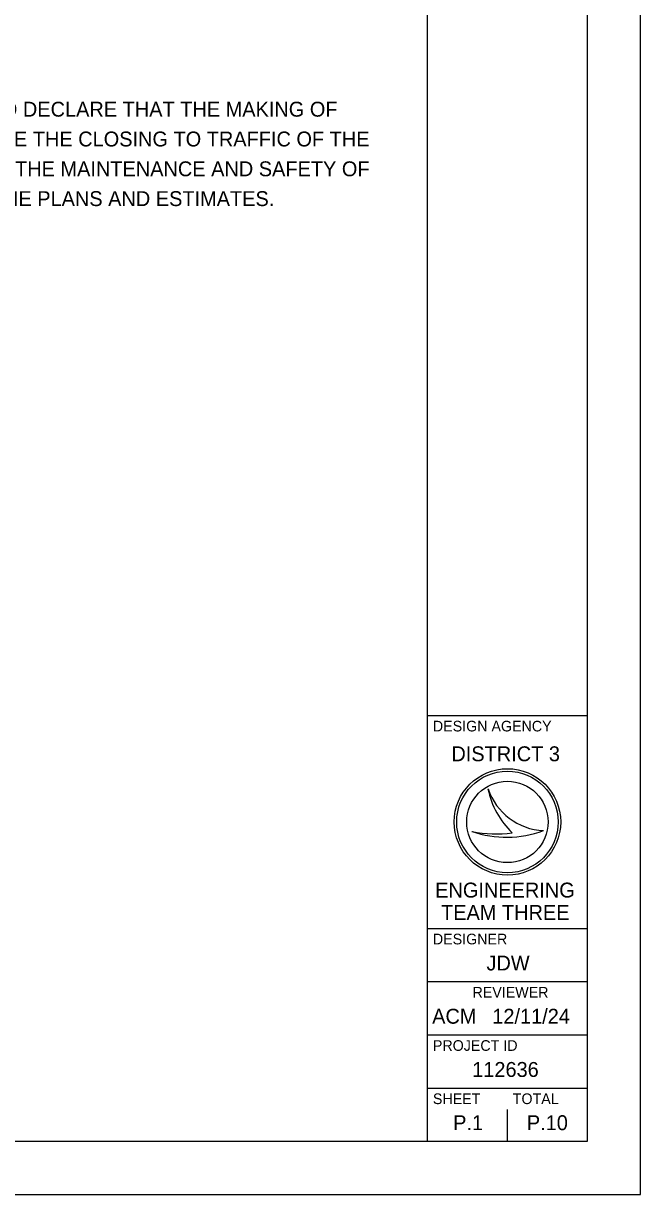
# Model space of a CAD drawing. Extents: x 0 to 170000, y 0 to 110000.
# Drawn here: x 141026 to 170000, y 0 to 55000 of the extents above; entities that cross this region are included whole.
import ezdxf

# ---------------------------------------------------------------- set-up
doc = ezdxf.new("R2010")
doc.units = 0
for name, color, linetype in [('SH_Border', 7, 'Continuous'), ('SH_Cut_Line', 7, 'Continuous'), ('SH_Data', 7, 'Continuous'), ('SH_Text', 7, 'Continuous')]:
    doc.layers.add(name, color=color, linetype=linetype)

msp = doc.modelspace()

# ---------------------------------------------------------------- linework, layer by layer
at = {"layer": 'SH_Border'}
for p, q in [((160000, 2500), (160000, 107500)), ((160000, 22500), (167500, 22500)), ((160000, 12500), (167500, 12500)), ((160000, 10000), (167500, 10000)), ((160000, 7500), (167500, 7500)), ((160000, 5000), (167500, 5000))]:
    msp.add_line(p, q, dxfattribs=at)
msp.add_lwpolyline([(7500, 107500), (167500, 107500), (167500, 2500), (7500, 2500)], close=True, dxfattribs=at)
at = {"layer": 'SH_Cut_Line'}
msp.add_lwpolyline([(0, 0), (170000, 0), (170000, 110000), (0, 110000)], close=True, dxfattribs=at)
at = {"layer": 'SH_Data'}
for p, q in [((162837, 19048), (162837, 19048)), ((163750, 17500), (163750, 17500)), ((165436, 17093), (165437, 17093)), ((162086, 17048), (162086, 17048)), ((163750, 2500), (163750, 4000)), ((161875, 3375), (161875, 3375))]:
    msp.add_line(p, q, dxfattribs=at)
for radius in [2500, 2384, 2384, 1911]:
    msp.add_circle((163750, 17500), radius, dxfattribs=at)
for centre, radius, start, end in [((165580, 19988), 2899, 198.9257, 198.9319), ((166733, 19850), 3978, 191.6379, 191.6421), ((165580, 19988), 2899, 198.9319, 267.1657), ((166733, 19850), 3978, 191.6421, 226.0947), ((163697, 21850), 5066, 251.4576, 290.0832), ((163240, 23272), 6330, 259.4964, 259.4995), ((163697, 21850), 5066, 251.4527, 251.4576), ((163240, 23272), 6330, 259.4995, 276.6672)]:
    msp.add_arc(centre, radius, start, end, dxfattribs=at)

# ---------------------------------------------------------------- texts
for s, height, p in [('DESIGN AGENCY', 500, (160250, 21750)), ('DISTRICT 3', 700, (161118, 20350)), ('ENGINEERING', 700, (160357, 13950)), ('TEAM THREE', 700, (160633, 12900)), ('DESIGNER', 500, (160250, 11750)), ('JDW', 700, (162765, 10525)), ('REVIEWER', 500, (162109, 9250)), ('ACM', 700, (160215, 8025)), ('12/11/24', 700, (163039, 8025)), ('PROJECT ID', 500, (160250, 6750)), ('112636', 700, (162096, 5525)), ('SHEET', 500, (160250, 4250)), ('TOTAL', 500, (164000, 4250)), ('P.1', 700, (161201, 3025)), ('P.10', 700, (164661, 3025))]:
    msp.add_text(s, height=height, dxfattribs=at).set_placement(p)
at = {"layer": 'SH_Text'}
for s, p in [('I HEREBY APPROVE THESE PLANS AND DECLARE THAT THE MAKING OF', (122639, 50622)), ('THIS IMPROVEMENT WILL NOT REQUIRE THE CLOSING TO TRAFFIC OF THE', (122639, 49222)), ('HIGHWAY AND THAT PROVISIONS FOR THE MAINTENANCE AND SAFETY OF', (122639, 47822)), ('TRAFFIC WILL BE AS SET FORTH ON THE PLANS AND ESTIMATES.', (122639, 46422))]:
    msp.add_text(s, height=700, dxfattribs=at).set_placement(p)

doc.saveas('drawing.dxf')
